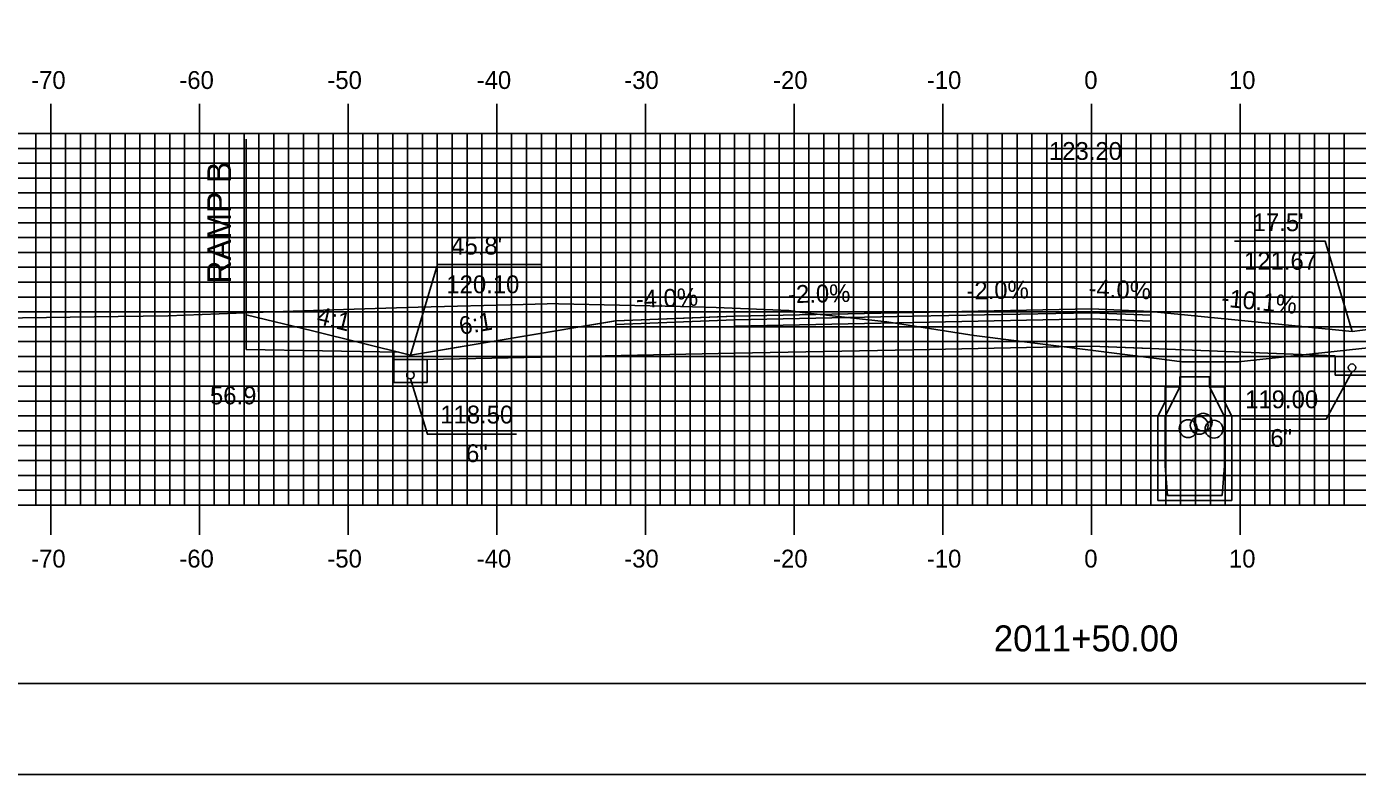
# Model space of a CAD drawing. Extents: x 853894 to 854237, y 366605 to 366825.
# Drawn here: x 853987.9 to 854077.4, y 366604.9 to 366655.2 of the extents above; entities that cross this region are included whole.
import ezdxf

# ---------------------------------------------------------------- set-up
doc = ezdxf.new("R2010")
doc.units = 0
for name, color, linetype in [('ANNOTATION', 7, 'Continuous'), ('BORDER', 7, 'Continuous'), ('D_Roadway_Centerline', 7, 'Continuous'), ('D_Roadway_Centerline_Text', 7, 'Continuous'), ('D_Roadway_Edge_Shoulder', 7, 'Continuous'), ('D_Roadway_Edge_TW', 7, 'Continuous'), ('D_Roadway_Pavement', 7, 'Continuous'), ('D_Roadway_SubGrade', 7, 'Continuous'), ('D_Text_Standard', 7, 'Continuous'), ('H_V ANNOTATION', 7, 'Continuous'), ('M_Roadway_Centerline', 7, 'Continuous'), ('MAJOR', 7, 'Continuous'), ('MINOR', 7, 'Continuous'), ('PDRAIN', 7, 'Continuous'), ('PLOT BOUNDARY', 7, 'Continuous'), ('S_Drainage_CB', 7, 'Continuous'), ('S_Drainage_Invert', 7, 'Continuous'), ('S_Roadway_Centerline', 7, 'Continuous')]:
    doc.layers.add(name, color=color, linetype=linetype)

msp = doc.modelspace()

# ---------------------------------------------------------------- linework, layer by layer
at = {"layer": 'ANNOTATION'}
for points in [[(854069.153, 366640.814), (854075.241, 366640.814), (854077.058, 366634.729)], [(854022.471, 366639.236), (854015.542, 366639.236), (854013.724, 366633.15)], [(854020.865, 366627.821), (854014.87, 366627.821), (854013.723, 366631.555)], [(854069.628, 366628.845), (854075.328, 366628.845), (854077.058, 366632.055)]]:
    msp.add_lwpolyline(points, dxfattribs=at)
at = {"layer": 'BORDER'}
msp.add_lwpolyline([(853909.93, 366611.055), (854229.93, 366611.055), (854229.93, 366821.055), (853909.93, 366821.055)], close=True, dxfattribs=at)
at = {"layer": 'D_Roadway_Centerline'}
msp.add_line((854059.53, 366633.751), (854075.933, 366633.095), dxfattribs=at)
for points in [[(854002.673, 366635.868), (854007.137, 366634.77), (854013.723, 366633.151)], [(854013.723, 366633.151), (854027.521, 366635.45), (854027.53, 366635.451), (854035.01, 366635.75), (854035.53, 366635.771), (854047.528, 366636.011), (854047.53, 366636.011), (854059.527, 366636.251), (854059.53, 366636.251), (854063.529, 366636.091), (854063.53, 366636.091), (854063.535, 366636.091), (854077.058, 366634.728)], [(854063.53, 366636.091), (854077.058, 366634.728)], [(854077.058, 366634.729), (854084.015, 366635.629), (854089.257, 366636.306)]]:
    msp.add_lwpolyline(points, dxfattribs=at)
at = {"layer": 'D_Roadway_Edge_Shoulder'}
for points in [[(854035.53, 366635.771), (854027.53, 366635.451), (854027.53, 366635.201), (854035.53, 366635.521)], [(854059.53, 366636.251), (854063.53, 366636.091), (854063.53, 366635.841), (854059.53, 366636.001)]]:
    msp.add_lwpolyline(points, close=True, dxfattribs=at)
at = {"layer": 'D_Roadway_Edge_TW'}
for points in [[(854047.53, 366636.011), (854035.53, 366635.771), (854035.53, 366635.521), (854047.53, 366635.761)], [(854059.53, 366636.251), (854047.53, 366636.011), (854047.53, 366635.761), (854059.53, 366636.001)]]:
    msp.add_lwpolyline(points, close=True, dxfattribs=at)
at = {"layer": 'D_Roadway_Pavement'}
for points in [[(854047.53, 366635.761), (854035.53, 366635.521), (854035.53, 366635.104), (854047.53, 366635.344)], [(854059.53, 366636.001), (854047.53, 366635.761), (854047.53, 366635.344), (854059.53, 366635.584)], [(854059.53, 366636.001), (854063.53, 366635.841), (854063.53, 366635.424), (854059.53, 366635.584)], [(854035.53, 366635.521), (854035.53, 366635.104), (854035.53, 366635.104)]]:
    msp.add_lwpolyline(points, close=True, dxfattribs=at)
msp.add_lwpolyline([(854047.53, 366635.761), (854047.53, 366635.344)], dxfattribs=at)
at = {"layer": 'D_Roadway_SubGrade'}
for p, q in [((854002.673, 366647.676), (854002.673, 366633.535)), ((854002.673, 366635.868), (854002.673, 366633.535)), ((854014.848, 366632.858), (854012.598, 366632.858))]:
    msp.add_line(p, q, dxfattribs=at)
for points in [[(854059.53, 366635.584), (854063.53, 366635.424), (854063.53, 366635.841), (854063.53, 366636.091), (854063.53, 366633.591), (854059.53, 366633.751)], [(854047.53, 366635.344), (854035.53, 366635.104), (854035.53, 366633.271), (854047.53, 366633.511)], [(854059.53, 366635.584), (854047.53, 366635.344), (854047.53, 366633.511), (854059.53, 366633.751)]]:
    msp.add_lwpolyline(points, close=True, dxfattribs=at)
for points in [[(854014.848, 366632.858), (854035.53, 366633.271), (854035.53, 366635.104), (854035.53, 366635.104), (854035.53, 366635.521), (854027.53, 366635.201), (854027.53, 366635.451), (854013.724, 366633.15)], [(854002.673, 366633.535), (854012.943, 366633.342)]]:
    msp.add_lwpolyline(points, dxfattribs=at)
at = {"layer": 'MAJOR'}
for p, q in [((853989.53, 366650.059), (853989.53, 366648.055)), ((853999.53, 366650.059), (853999.53, 366648.055)), ((854009.53, 366650.059), (854009.53, 366648.055)), ((854019.53, 366650.059), (854019.53, 366648.055)), ((854029.53, 366650.059), (854029.53, 366648.055)), ((854039.53, 366650.059), (854039.53, 366648.055)), ((854049.53, 366650.059), (854049.53, 366648.055)), ((854059.53, 366650.059), (854059.53, 366648.055)), ((854069.53, 366650.059), (854069.53, 366648.055)), ((853919.53, 366648.055), (854199.53, 366648.055)), ((853919.53, 366648.055), (854199.53, 366648.055)), ((853989.53, 366623.055), (853989.53, 366648.055)), ((853999.53, 366623.055), (853999.53, 366648.055)), ((854009.53, 366623.055), (854009.53, 366648.055)), ((854019.53, 366623.055), (854019.53, 366648.055)), ((854029.53, 366623.055), (854029.53, 366648.055)), ((854039.53, 366623.055), (854039.53, 366648.055)), ((854049.53, 366623.055), (854049.53, 366648.055)), ((854059.53, 366623.055), (854059.53, 366648.055)), ((854069.53, 366623.055), (854069.53, 366648.055)), ((853919.53, 366643.055), (854199.53, 366643.055)), ((853919.53, 366638.055), (854199.53, 366638.055)), ((853919.53, 366633.055), (854199.53, 366633.055)), ((853919.53, 366628.055), (854199.53, 366628.055)), ((853919.53, 366623.055), (854199.53, 366623.055)), ((853919.53, 366623.055), (854199.53, 366623.055)), ((853989.53, 366621.051), (853989.53, 366623.055)), ((853999.53, 366621.051), (853999.53, 366623.055)), ((854009.53, 366621.051), (854009.53, 366623.055)), ((854019.53, 366621.051), (854019.53, 366623.055)), ((854029.53, 366621.051), (854029.53, 366623.055)), ((854039.53, 366621.051), (854039.53, 366623.055)), ((854049.53, 366621.051), (854049.53, 366623.055)), ((854059.53, 366621.051), (854059.53, 366623.055)), ((854069.53, 366621.051), (854069.53, 366623.055))]:
    msp.add_line(p, q, dxfattribs=at)
at = {"layer": 'MINOR'}
for p, q in [((853988.53, 366623.055), (853988.53, 366648.055)), ((853990.53, 366623.055), (853990.53, 366648.055)), ((853991.53, 366623.055), (853991.53, 366648.055)), ((853992.53, 366623.055), (853992.53, 366648.055)), ((853993.53, 366623.055), (853993.53, 366648.055)), ((853994.53, 366623.055), (853994.53, 366648.055)), ((853995.53, 366623.055), (853995.53, 366648.055)), ((853996.53, 366623.055), (853996.53, 366648.055)), ((853997.53, 366623.055), (853997.53, 366648.055)), ((853998.53, 366623.055), (853998.53, 366648.055)), ((854000.53, 366623.055), (854000.53, 366648.055)), ((854001.53, 366623.055), (854001.53, 366648.055)), ((854002.53, 366623.055), (854002.53, 366648.055)), ((854003.53, 366623.055), (854003.53, 366648.055)), ((854004.53, 366623.055), (854004.53, 366648.055)), ((854005.53, 366623.055), (854005.53, 366648.055)), ((854006.53, 366623.055), (854006.53, 366648.055)), ((854007.53, 366623.055), (854007.53, 366648.055)), ((854008.53, 366623.055), (854008.53, 366648.055)), ((854010.53, 366623.055), (854010.53, 366648.055)), ((854011.53, 366623.055), (854011.53, 366648.055)), ((854012.53, 366623.055), (854012.53, 366648.055)), ((854013.53, 366623.055), (854013.53, 366648.055)), ((854014.53, 366623.055), (854014.53, 366648.055)), ((854015.53, 366623.055), (854015.53, 366648.055)), ((854016.53, 366623.055), (854016.53, 366648.055)), ((854017.53, 366623.055), (854017.53, 366648.055)), ((854018.53, 366623.055), (854018.53, 366648.055)), ((854020.53, 366623.055), (854020.53, 366648.055)), ((854021.53, 366623.055), (854021.53, 366648.055)), ((854022.53, 366623.055), (854022.53, 366648.055)), ((854023.53, 366623.055), (854023.53, 366648.055)), ((854024.53, 366623.055), (854024.53, 366648.055)), ((854025.53, 366623.055), (854025.53, 366648.055)), ((854026.53, 366623.055), (854026.53, 366648.055)), ((854027.53, 366623.055), (854027.53, 366648.055)), ((854028.53, 366623.055), (854028.53, 366648.055)), ((854030.53, 366623.055), (854030.53, 366648.055)), ((854031.53, 366623.055), (854031.53, 366648.055)), ((854032.53, 366623.055), (854032.53, 366648.055)), ((854033.53, 366623.055), (854033.53, 366648.055)), ((854034.53, 366623.055), (854034.53, 366648.055)), ((854035.53, 366623.055), (854035.53, 366648.055)), ((854036.53, 366623.055), (854036.53, 366648.055)), ((854037.53, 366623.055), (854037.53, 366648.055)), ((854038.53, 366623.055), (854038.53, 366648.055)), ((854040.53, 366623.055), (854040.53, 366648.055)), ((854041.53, 366623.055), (854041.53, 366648.055)), ((854042.53, 366623.055), (854042.53, 366648.055)), ((854043.53, 366623.055), (854043.53, 366648.055)), ((854044.53, 366623.055), (854044.53, 366648.055)), ((854045.53, 366623.055), (854045.53, 366648.055)), ((854046.53, 366623.055), (854046.53, 366648.055)), ((854047.53, 366623.055), (854047.53, 366648.055)), ((854048.53, 366623.055), (854048.53, 366648.055)), ((854050.53, 366623.055), (854050.53, 366648.055)), ((854051.53, 366623.055), (854051.53, 366648.055)), ((854052.53, 366623.055), (854052.53, 366648.055)), ((854053.53, 366623.055), (854053.53, 366648.055)), ((854054.53, 366623.055), (854054.53, 366648.055)), ((854055.53, 366623.055), (854055.53, 366648.055)), ((854056.53, 366623.055), (854056.53, 366648.055)), ((854057.53, 366623.055), (854057.53, 366648.055)), ((854058.53, 366623.055), (854058.53, 366648.055)), ((854060.53, 366623.055), (854060.53, 366648.055)), ((854061.53, 366623.055), (854061.53, 366648.055)), ((854062.53, 366623.055), (854062.53, 366648.055)), ((854063.53, 366623.055), (854063.53, 366648.055)), ((854064.53, 366623.055), (854064.53, 366648.055)), ((854065.53, 366623.055), (854065.53, 366648.055)), ((854066.53, 366623.055), (854066.53, 366648.055)), ((854067.53, 366623.055), (854067.53, 366648.055)), ((854068.53, 366623.055), (854068.53, 366648.055)), ((854070.53, 366623.055), (854070.53, 366648.055)), ((854071.53, 366623.055), (854071.53, 366648.055)), ((854072.53, 366623.055), (854072.53, 366648.055)), ((854073.53, 366623.055), (854073.53, 366648.055)), ((854074.53, 366623.055), (854074.53, 366648.055)), ((854075.53, 366623.055), (854075.53, 366648.055)), ((854076.53, 366623.055), (854076.53, 366648.055)), ((853919.53, 366647.055), (854199.53, 366647.055)), ((853919.53, 366646.055), (854199.53, 366646.055)), ((853919.53, 366645.055), (854199.53, 366645.055)), ((853919.53, 366644.055), (854199.53, 366644.055)), ((853919.53, 366642.055), (854199.53, 366642.055)), ((853919.53, 366641.055), (854199.53, 366641.055)), ((853919.53, 366640.055), (854199.53, 366640.055)), ((853919.53, 366639.055), (854199.53, 366639.055)), ((853919.53, 366637.055), (854199.53, 366637.055)), ((853919.53, 366636.055), (854199.53, 366636.055)), ((853919.53, 366635.055), (854199.53, 366635.055)), ((853919.53, 366634.055), (854199.53, 366634.055)), ((853919.53, 366632.055), (854199.53, 366632.055)), ((853919.53, 366631.055), (854199.53, 366631.055)), ((853919.53, 366630.055), (854199.53, 366630.055)), ((853919.53, 366629.055), (854199.53, 366629.055)), ((853919.53, 366627.055), (854199.53, 366627.055)), ((853919.53, 366626.055), (854199.53, 366626.055)), ((853919.53, 366625.055), (854199.53, 366625.055)), ((853919.53, 366624.055), (854199.53, 366624.055))]:
    msp.add_line(p, q, dxfattribs=at)
at = {"layer": 'PDRAIN'}
for points in [[(854012.598, 366633.349), (854012.598, 366631.305), (854014.848, 366631.305), (854014.848, 366632.858)], [(854075.933, 366633.095), (854075.933, 366631.805), (854078.183, 366631.805), (854078.183, 366633.66)]]:
    msp.add_lwpolyline(points, dxfattribs=at)
for centre in [(854077.058, 366632.305), (854013.723, 366631.805)]:
    msp.add_circle(centre, 0.25, dxfattribs=at)
at = {"layer": 'PLOT BOUNDARY'}
msp.add_lwpolyline([(853893.743, 366604.937), (854233.743, 366604.937), (854233.743, 366824.937), (853893.743, 366824.937)], close=True, dxfattribs=at)
at = {"layer": 'S_Drainage_CB'}
for p, q in [((854065.468, 366631.02), (854064.484, 366631.02)), ((854064.484, 366631.02), (854064.484, 366630.036)), ((854064.484, 366629.019), (854065.468, 366631.02)), ((854068.487, 366631.02), (854067.47, 366631.02)), ((854067.47, 366631.02), (854068.487, 366629.019)), ((854068.487, 366630.036), (854068.487, 366631.02)), ((854064.484, 366630.036), (854063.992, 366629.019)), ((854068.979, 366629.019), (854068.487, 366630.036)), ((854063.992, 366629.019), (854063.992, 366623.376)), ((854064.484, 366625.705), (854064.484, 366629.019)), ((854068.487, 366629.019), (854068.487, 366625.705)), ((854068.979, 366623.376), (854068.979, 366629.019)), ((854064.648, 366623.704), (854064.484, 366625.705)), ((854068.487, 366625.705), (854068.323, 366623.704)), ((854063.992, 366623.376), (854068.979, 366623.376)), ((854068.323, 366623.704), (854064.648, 366623.704))]:
    msp.add_line(p, q, dxfattribs=at)
msp.add_lwpolyline([(854067.962, 366631.062), (854067.47, 366631.062), (854067.47, 366631.685), (854065.468, 366631.685), (854065.468, 366631.062), (854064.976, 366631.062)], dxfattribs=at)
at = {"layer": 'S_Drainage_Invert'}
for centre in [(854066.035, 366628.201), (854066.781, 366628.418), (854067.048, 366628.631), (854067.776, 366628.16)]:
    msp.add_circle(centre, 0.6, dxfattribs=at)
at = {"layer": 'S_Roadway_Centerline'}
msp.add_lwpolyline([(853985.984, 366635.626), (853994.07, 366635.744), (853997.435, 366635.79), (854003.149, 366636.017), (854009.233, 366636.206), (854012.776, 366636.319), (854014.251, 366636.363), (854021.314, 366636.559), (854022.922, 366636.593), (854023.55, 366636.614), (854023.675, 366636.594), (854031.899, 366636.419), (854034.285, 366636.346), (854039.169, 366636.151), (854040.083, 366636.014), (854045.763, 366635.385), (854051.649, 366634.471), (854064.438, 366632.849), (854065.606, 366632.693), (854069.274, 366632.685), (854069.433, 366632.703), (854070.019, 366632.766), (854087.925, 366634.686)], dxfattribs=at)

# ---------------------------------------------------------------- texts
at = {"layer": 'ANNOTATION'}
for s, height, rotation, p in [('RAMP B', 1.6, 90, (854001.66, 366637.961)), ('-4.0%', 1.2, 2.29061, (854028.902, 366636.308)), ('-2.0%', 1.2, 1.14577, (854039.135, 366636.644)), ('-2.0%', 1.2, 1.14577, (854051.134, 366636.884)), ('-4.0%', 1.2, 357.70974, (854059.321, 366637.061)), ('-10.1%', 1.2, 354.24653, (854068.229, 366636.428)), ('4:1', 1.2, 346.18377, (854007.346, 366635.269)), ('6:1', 1.2, 9.46089, (854017.099, 366634.505)), ('119.00', 1.2, 360, (854069.871, 366629.571)), ('118.50', 1.2, 360, (854015.729, 366628.547)), ('6"', 1.2, 360, (854071.562, 366626.971)), ('6"', 1.2, 360, (854017.462, 366625.947))]:
    msp.add_text(s, height=height, rotation=rotation, dxfattribs=at).set_placement(p)
for s, p in [("17.5' ", (854070.378, 366641.488)), ("45.8' ", (854016.466, 366639.91)), ('121.67', (854069.795, 366638.888)), ('120.10', (854016.14, 366637.31))]:
    msp.add_text(s, height=1.2, dxfattribs=at).set_placement(p)
at = {"layer": 'D_Roadway_Centerline_Text'}
msp.add_text('123.20', height=1.2, dxfattribs=at).set_placement((854056.673, 366646.281))
at = {"layer": 'D_Text_Standard'}
msp.add_text("56.9'", height=1.2, dxfattribs=at).set_placement((854000.239, 366629.836))
at = {"layer": 'H_V ANNOTATION'}
for s, height, p in [('-70', 1.2, (853988.213, 366651.055)), ('-60', 1.2, (853998.181, 366651.055)), ('-50', 1.2, (854008.138, 366651.055)), ('-40', 1.2, (854018.181, 366651.055)), ('-30', 1.2, (854028.106, 366651.055)), ('-20', 1.2, (854038.117, 366651.055)), ('-10', 1.2, (854048.46, 366651.055)), ('0', 1.2, (854059.048, 366651.055)), ('10', 1.2, (854068.781, 366651.055)), ('-70', 1.2, (853988.213, 366618.855)), ('-60', 1.2, (853998.181, 366618.855)), ('-50', 1.2, (854008.138, 366618.855)), ('-40', 1.2, (854018.181, 366618.855)), ('-30', 1.2, (854028.106, 366618.855)), ('-20', 1.2, (854038.117, 366618.855)), ('-10', 1.2, (854048.46, 366618.855)), ('0', 1.2, (854059.048, 366618.855)), ('10', 1.2, (854068.781, 366618.855)), ('2011+50.00', 1.75, (854052.96, 366613.211))]:
    msp.add_text(s, height=height, dxfattribs=at).set_placement(p)
at = {"layer": 'M_Roadway_Centerline'}
for s, p in [('C', (854023.545, 366636.614)), ('L', (854023.55, 366636.607))]:
    msp.add_text(s, height=0.0146, dxfattribs=at).set_placement(p)

doc.saveas('drawing.dxf')
